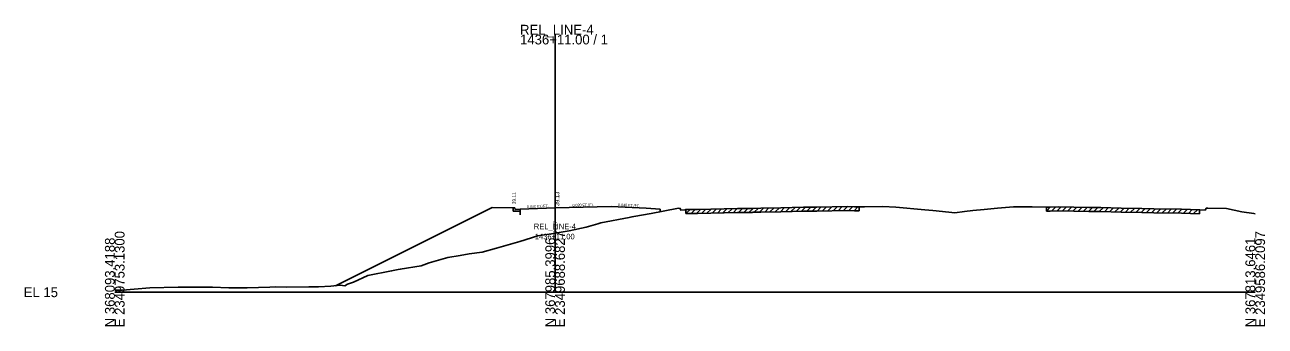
# Model space of a CAD drawing. Extents: x -26 to 2350146, y -10 to 368200.
# Drawn here: x 974.3 to 1328.6, y 7990.3 to 8076.4 of the extents above; entities that cross this region are included whole.
import ezdxf

# ---------------------------------------------------------------- set-up
doc = ezdxf.new("R2010")
doc.units = 0
for name, color, linetype in [('RD_GPK_XS_Cell', 7, 'Continuous'), ('RD_XS_CurbBase', 7, 'Continuous'), ('RD_XS_CurbFront', 7, 'Continuous'), ('RD_XS_CurbTop', 7, 'Continuous'), ('RD_XS_EarthShd', 7, 'Continuous'), ('RD_XS_ExGround', 7, 'Continuous'), ('RD_XS_ExPaveRet', 7, 'Continuous'), ('RD_XS_MatchLine', 7, 'Continuous'), ('RD_XS_Pave', 7, 'Continuous'), ('RD_XS_PaveShd', 7, 'Continuous'), ('RD_XS_TieSlope', 7, 'Continuous'), ('RD_XS_TX_Elev_EX', 7, 'Continuous'), ('RD_XS_TX_Elev_PR', 7, 'Continuous'), ('RD_XS_TX_Slope', 7, 'Continuous'), ('RD_XS_TX_Station', 7, 'Continuous'), ('RD_XS_TX_TOC', 7, 'Continuous')]:
    doc.layers.add(name, color=color, linetype=linetype)

msp = doc.modelspace()

# ---------------------------------------------------------------- linework, layer by layer
at = {"layer": 'RD_GPK_XS_Cell'}
for p, q in [((1125.78, 8000), (1125.78, 8073.59)), ((1000, 8000), (1125.78, 8000)), ((1125.78, 8000), (1325.78, 8000))]:
    msp.add_line(p, q, dxfattribs=at)
at = {"layer": 'RD_XS_CurbBase'}
for p, q in [((1113.78, 8024.13), (1113.78, 8023.13)), ((1113.78, 8023.13), (1114.28, 8023.13)), ((1114.28, 8023.13), (1115.78, 8023.21)), ((1115.78, 8022.15), (1115.78, 8023.21))]:
    msp.add_line(p, q, dxfattribs=at)
at = {"layer": 'RD_XS_CurbFront'}
msp.add_line((1115.78, 8023.21), (1115.78, 8023.71), dxfattribs=at)
at = {"layer": 'RD_XS_CurbTop'}
for p, q in [((1114.28, 8024.13), (1113.78, 8024.13)), ((1114.37, 8023.63), (1114.28, 8024.13)), ((1115.78, 8023.71), (1114.37, 8023.63)), ((1115.78, 8023.73), (1115.78, 8023.71))]:
    msp.add_line(p, q, dxfattribs=at)
at = {"layer": 'RD_XS_EarthShd'}
for p, q in [((1113.78, 8024.13), (1107.78, 8024.25)), ((1151.78, 8024.05), (1155.78, 8023.73))]:
    msp.add_line(p, q, dxfattribs=at)
at = {"layer": 'RD_XS_ExGround'}
msp.add_lwpolyline([(1000, 8000.6), (1002.21, 8000.55), (1005.58, 8000.89), (1010.03, 8001.29), (1018.14, 8001.5), (1022.61, 8001.5), (1027.93, 8001.5), (1032.55, 8001.22), (1037.85, 8001.29), (1044.26, 8001.44), (1045.82, 8001.51), (1049.03, 8001.44), (1055.44, 8001.51), (1058.24, 8001.55), (1061.68, 8001.73), (1064.39, 8002.02), (1065.74, 8001.88), (1066.46, 8002.27), (1068.24, 8002.9), (1072.26, 8004.82), (1079.06, 8006.1), (1080.97, 8006.5), (1081.55, 8006.58), (1087.48, 8007.57), (1089.83, 8008.39), (1095.12, 8009.95), (1098.66, 8010.51), (1101.24, 8010.98), (1104.95, 8011.49), (1109.06, 8012.57), (1115.75, 8014.5), (1119.04, 8015.52), (1120.73, 8016.12), (1125.4, 8016.81), (1125.78, 8016.87), (1129.79, 8017.57), (1134.69, 8018.64), (1137.96, 8019.57), (1138.86, 8019.81), (1146.97, 8021.37), (1147.72, 8021.5), (1148.25, 8021.62), (1153.18, 8022.51), (1160.58, 8023.9), (1161.09, 8023.99), (1161.52, 8023.97), (1161.68, 8023.48), (1162.92, 8023.52), (1163.17, 8023.6), (1163.48, 8023.6), (1166.46, 8023.67), (1177.85, 8023.88), (1182.09, 8023.96), (1182.4, 8023.97), (1184.59, 8024.03), (1190.26, 8024.15), (1196.71, 8024.29), (1200.59, 8024.35), (1209.24, 8024.48), (1211.35, 8024.44), (1212.62, 8024.41), (1214.13, 8024.44), (1219.38, 8024.53), (1223.08, 8024.26), (1231.36, 8023.58), (1233.67, 8023.38), (1238.23, 8022.88), (1239.97, 8022.69), (1242.73, 8023.07), (1245.08, 8023.37), (1248.38, 8023.68), (1252.19, 8024.01), (1256.72, 8024.39), (1262.09, 8024.36), (1266.18, 8024.34), (1267.22, 8024.35), (1269.7, 8024.38), (1278.2, 8024.23), (1281.65, 8024.18), (1287.46, 8024.04), (1293.42, 8023.91), (1296.81, 8023.85), (1304.67, 8023.7), (1309.89, 8023.54), (1310.09, 8023.48), (1311.62, 8023.5), (1311.81, 8023.98), (1312.21, 8023.99), (1317.57, 8023.96), (1321.96, 8022.97), (1325.34, 8022.48), (1325.78, 8022.36)], dxfattribs=at)
at = {"layer": 'RD_XS_ExPaveRet'}
for p, q in [((1163.17, 8022.45), (1164.34, 8023.62)), ((1163.17, 8022.45), (1163.17, 8023.6)), ((1163.17, 8022.45), (1163.48, 8022.46)), ((1163.48, 8022.46), (1166.46, 8022.52)), ((1164.67, 8022.48), (1165.84, 8023.65)), ((1166.17, 8022.52), (1167.34, 8023.68)), ((1166.46, 8022.52), (1177.85, 8022.74)), ((1167.67, 8022.55), (1168.84, 8023.71)), ((1169.17, 8022.57), (1170.34, 8023.74)), ((1170.67, 8022.6), (1171.84, 8023.77)), ((1172.17, 8022.63), (1173.34, 8023.8)), ((1173.67, 8022.66), (1174.84, 8023.82)), ((1175.17, 8022.69), (1176.34, 8023.85)), ((1176.67, 8022.72), (1177.84, 8023.88)), ((1177.85, 8022.74), (1182.09, 8022.82)), ((1178.17, 8022.74), (1179.34, 8023.91)), ((1179.67, 8022.77), (1180.84, 8023.94)), ((1181.17, 8022.8), (1182.34, 8023.97)), ((1182.09, 8022.82), (1182.4, 8022.83)), ((1182.4, 8022.83), (1184.59, 8022.88)), ((1182.67, 8022.83), (1183.85, 8024.01)), ((1184.17, 8022.87), (1185.34, 8024.04)), ((1184.59, 8022.88), (1190.26, 8023.01)), ((1185.67, 8022.91), (1186.84, 8024.08)), ((1187.17, 8022.94), (1188.34, 8024.11)), ((1188.67, 8022.97), (1189.84, 8024.14)), ((1190.17, 8023.01), (1191.34, 8024.17)), ((1190.26, 8023.01), (1196.71, 8023.14)), ((1191.67, 8023.04), (1192.84, 8024.2)), ((1193.17, 8023.07), (1194.34, 8024.24)), ((1194.67, 8023.1), (1195.84, 8024.27)), ((1196.17, 8023.13), (1197.34, 8024.3)), ((1196.71, 8023.14), (1200.59, 8023.21)), ((1197.67, 8023.16), (1198.83, 8024.32)), ((1199.17, 8023.18), (1200.33, 8024.35)), ((1200.59, 8023.21), (1209.24, 8023.34)), ((1200.67, 8023.21), (1201.83, 8024.37)), ((1202.17, 8023.23), (1203.33, 8024.39)), ((1203.67, 8023.25), (1204.83, 8024.41)), ((1205.17, 8023.27), (1206.33, 8024.44)), ((1206.67, 8023.3), (1207.83, 8024.46)), ((1208.17, 8023.32), (1209.33, 8024.48)), ((1209.24, 8023.34), (1211.35, 8023.29)), ((1209.67, 8023.33), (1210.79, 8024.45)), ((1211.17, 8023.3), (1212.29, 8024.42)), ((1211.35, 8023.29), (1212.62, 8023.27)), ((1212.62, 8024.41), (1212.62, 8023.27)), ((1266.18, 8023.2), (1267.34, 8024.36)), ((1266.18, 8023.2), (1266.18, 8024.34)), ((1266.18, 8023.2), (1267.22, 8023.21)), ((1267.22, 8023.21), (1269.7, 8023.23)), ((1267.68, 8023.22), (1268.83, 8024.37)), ((1269.18, 8023.23), (1270.32, 8024.37)), ((1269.7, 8023.23), (1278.2, 8023.09)), ((1270.68, 8023.22), (1271.8, 8024.34)), ((1272.18, 8023.19), (1273.3, 8024.32)), ((1273.68, 8023.17), (1274.8, 8024.29)), ((1275.18, 8023.14), (1276.3, 8024.27)), ((1276.68, 8023.12), (1277.8, 8024.24)), ((1278.18, 8023.09), (1279.3, 8024.22)), ((1278.2, 8023.09), (1281.65, 8023.03)), ((1279.68, 8023.07), (1280.8, 8024.19)), ((1281.18, 8023.04), (1282.3, 8024.16)), ((1281.65, 8023.03), (1287.46, 8022.9)), ((1282.68, 8023.01), (1283.8, 8024.13)), ((1284.18, 8022.98), (1285.3, 8024.09)), ((1285.68, 8022.94), (1286.8, 8024.06)), ((1287.18, 8022.91), (1288.3, 8024.03)), ((1287.46, 8022.9), (1293.42, 8022.77)), ((1288.68, 8022.87), (1289.8, 8023.99)), ((1290.18, 8022.84), (1291.3, 8023.96)), ((1291.68, 8022.81), (1292.8, 8023.92)), ((1293.18, 8022.77), (1294.3, 8023.89)), ((1293.42, 8022.77), (1296.81, 8022.7)), ((1294.68, 8022.74), (1295.8, 8023.86)), ((1296.18, 8022.71), (1297.3, 8023.84)), ((1296.81, 8022.7), (1304.67, 8022.56)), ((1297.68, 8022.69), (1298.8, 8023.81)), ((1299.18, 8022.66), (1300.3, 8023.78)), ((1300.68, 8022.63), (1301.8, 8023.76)), ((1302.18, 8022.61), (1303.3, 8023.73)), ((1303.68, 8022.58), (1304.8, 8023.7)), ((1304.67, 8022.56), (1309.89, 8022.4)), ((1305.18, 8022.54), (1306.29, 8023.65)), ((1306.68, 8022.5), (1307.79, 8023.61)), ((1308.18, 8022.45), (1309.29, 8023.56)), ((1309.89, 8023.54), (1309.89, 8022.4))]:
    msp.add_line(p, q, dxfattribs=at)
at = {"layer": 'RD_XS_MatchLine'}
msp.add_line((1155.78, 8023), (1155.78, 8023.73), dxfattribs=at)
at = {"layer": 'RD_XS_Pave'}
for q in [(1115.78, 8023.73), (1141.78, 8024.45)]:
    msp.add_line((1125.78, 8024.13), q, dxfattribs=at)
at = {"layer": 'RD_XS_PaveShd'}
msp.add_line((1141.78, 8024.45), (1151.78, 8024.05), dxfattribs=at)
at = {"layer": 'RD_XS_TieSlope'}
msp.add_line((1107.78, 8024.25), (1063.04, 8001.87), dxfattribs=at)

# ---------------------------------------------------------------- texts
at = {"layer": 'RD_GPK_XS_Cell'}
for s, p in [('REL_LINE-4', (1115.78, 8073.59)), ('1436+11.00 / 1', (1115.78, 8070.79)), ('EL 15', (974, 7998.6))]:
    msp.add_text(s, height=2.8, dxfattribs=at).set_placement(p)
for s, p in [('N 368093.4188', (1000, 7990)), ('E 2349753.1300', (1002.8, 7990)), ('N 367985.3996', (1125.78, 7990)), ('E 2349688.6827', (1128.58, 7990)), ('N 367813.6461', (1325.78, 7990)), ('E 2349586.2097', (1328.58, 7990))]:
    msp.add_text(s, height=2.8, rotation=90, dxfattribs=at).set_placement(p)
at = {"layer": 'RD_XS_TX_Elev_EX'}
msp.add_text('31.87', height=1, rotation=90, dxfattribs=at).set_placement((1126.28, 8016.87))
at = {"layer": 'RD_XS_TX_Elev_PR'}
for s, height, p in [('39.11', 1, (1114.53, 8025.13)), (' 39.13', 1.2, (1126.98, 8024.13))]:
    msp.add_text(s, height=height, rotation=90, dxfattribs=at).set_placement(p)
at = {"layer": 'RD_XS_TX_Slope'}
for s, rotation, p in [('0.020 FT./FT.', 1.1458, (1130.75, 8024.48)), ('0.040 FT./FT.', 357.7094, (1143.77, 8024.62)), ('0.040 FT./FT.', 2.2906, (1117.75, 8024.06))]:
    msp.add_text(s, height=0.75, rotation=rotation, dxfattribs=at).set_placement(p)
at = {"layer": 'RD_XS_TX_Station'}
for s, p in [('REL_LINE-4', (1119.71, 8018.01)), ('1436+11.00', (1120.01, 8015.11))]:
    msp.add_text(s, height=1.6, dxfattribs=at).set_placement(p)
at = {"layer": 'RD_XS_TX_TOC'}
msp.add_text('TOCLT', height=0.05, dxfattribs=at).set_placement((1114.33, 8024.08))

doc.saveas('drawing.dxf')
